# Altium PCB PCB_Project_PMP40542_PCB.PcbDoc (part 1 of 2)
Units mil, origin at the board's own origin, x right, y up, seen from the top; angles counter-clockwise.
Board outline 1181.1 x 1181.1 mil, 4 copper layers (Top Layer, Signal Layer 1, Signal Layer 2, Bottom Layer), stack 42.8 mil thick; 61 components, 38 nets, 268 pads, 149 vias.
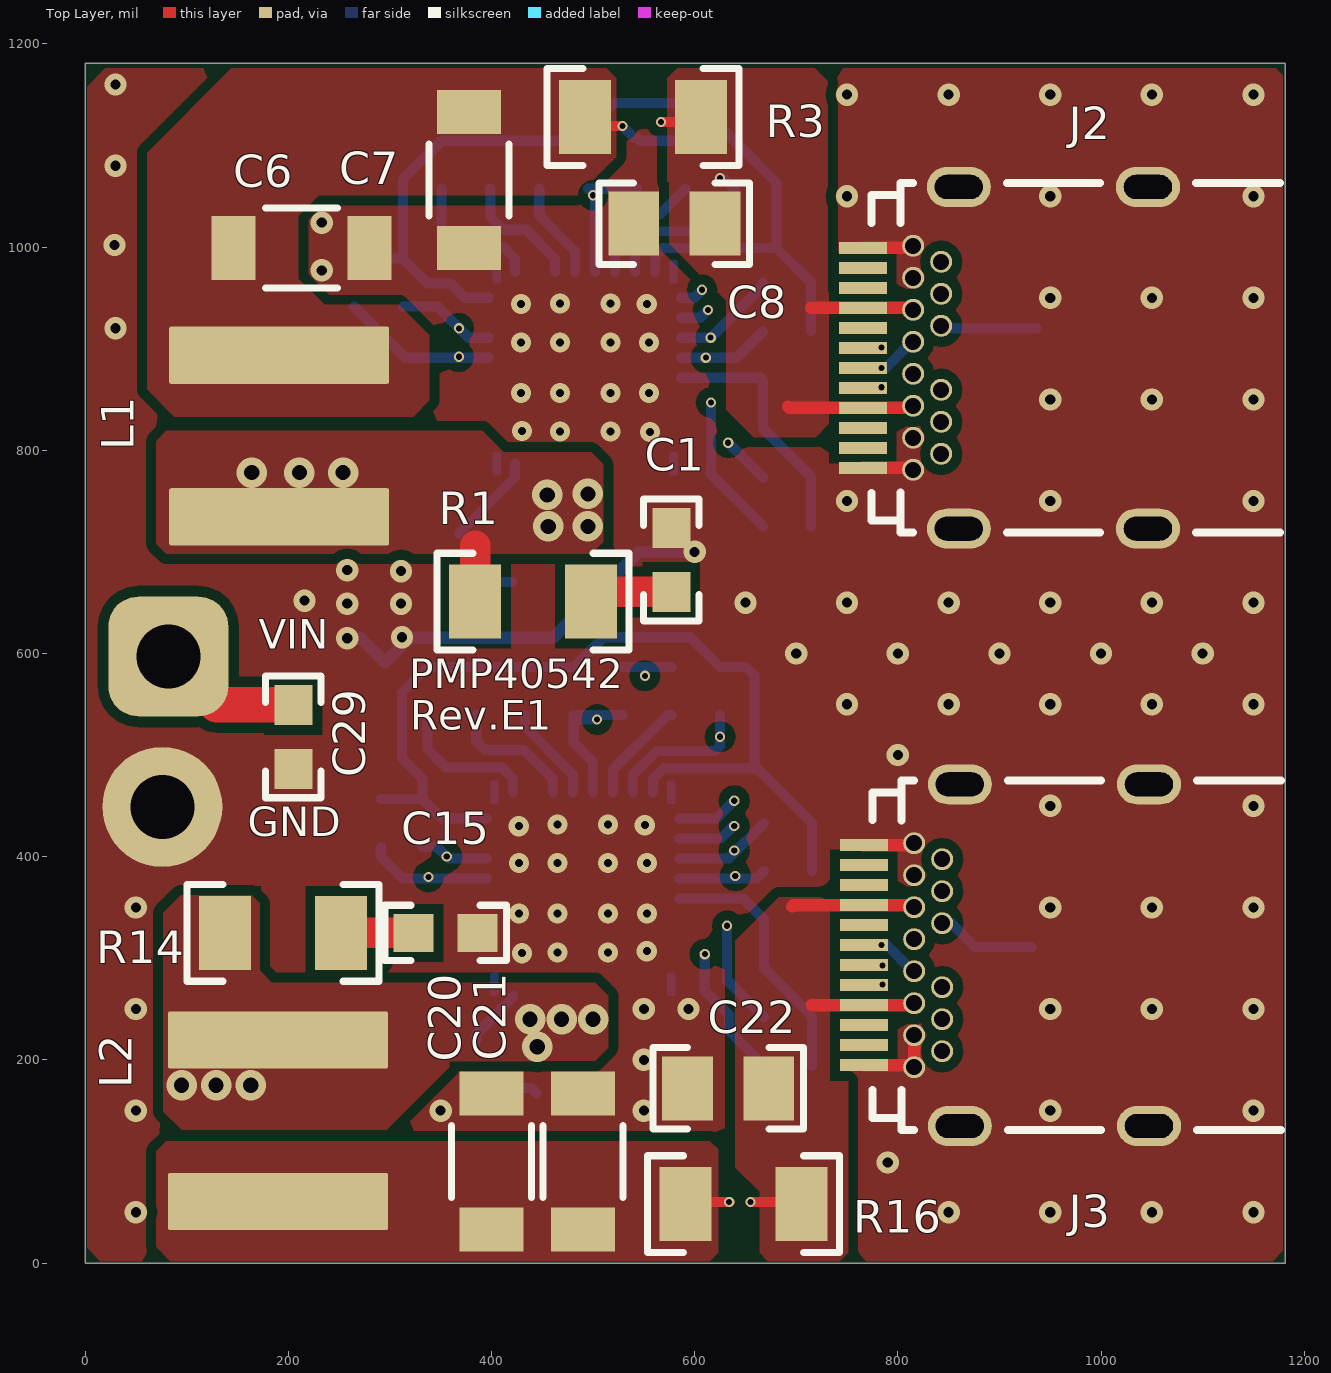
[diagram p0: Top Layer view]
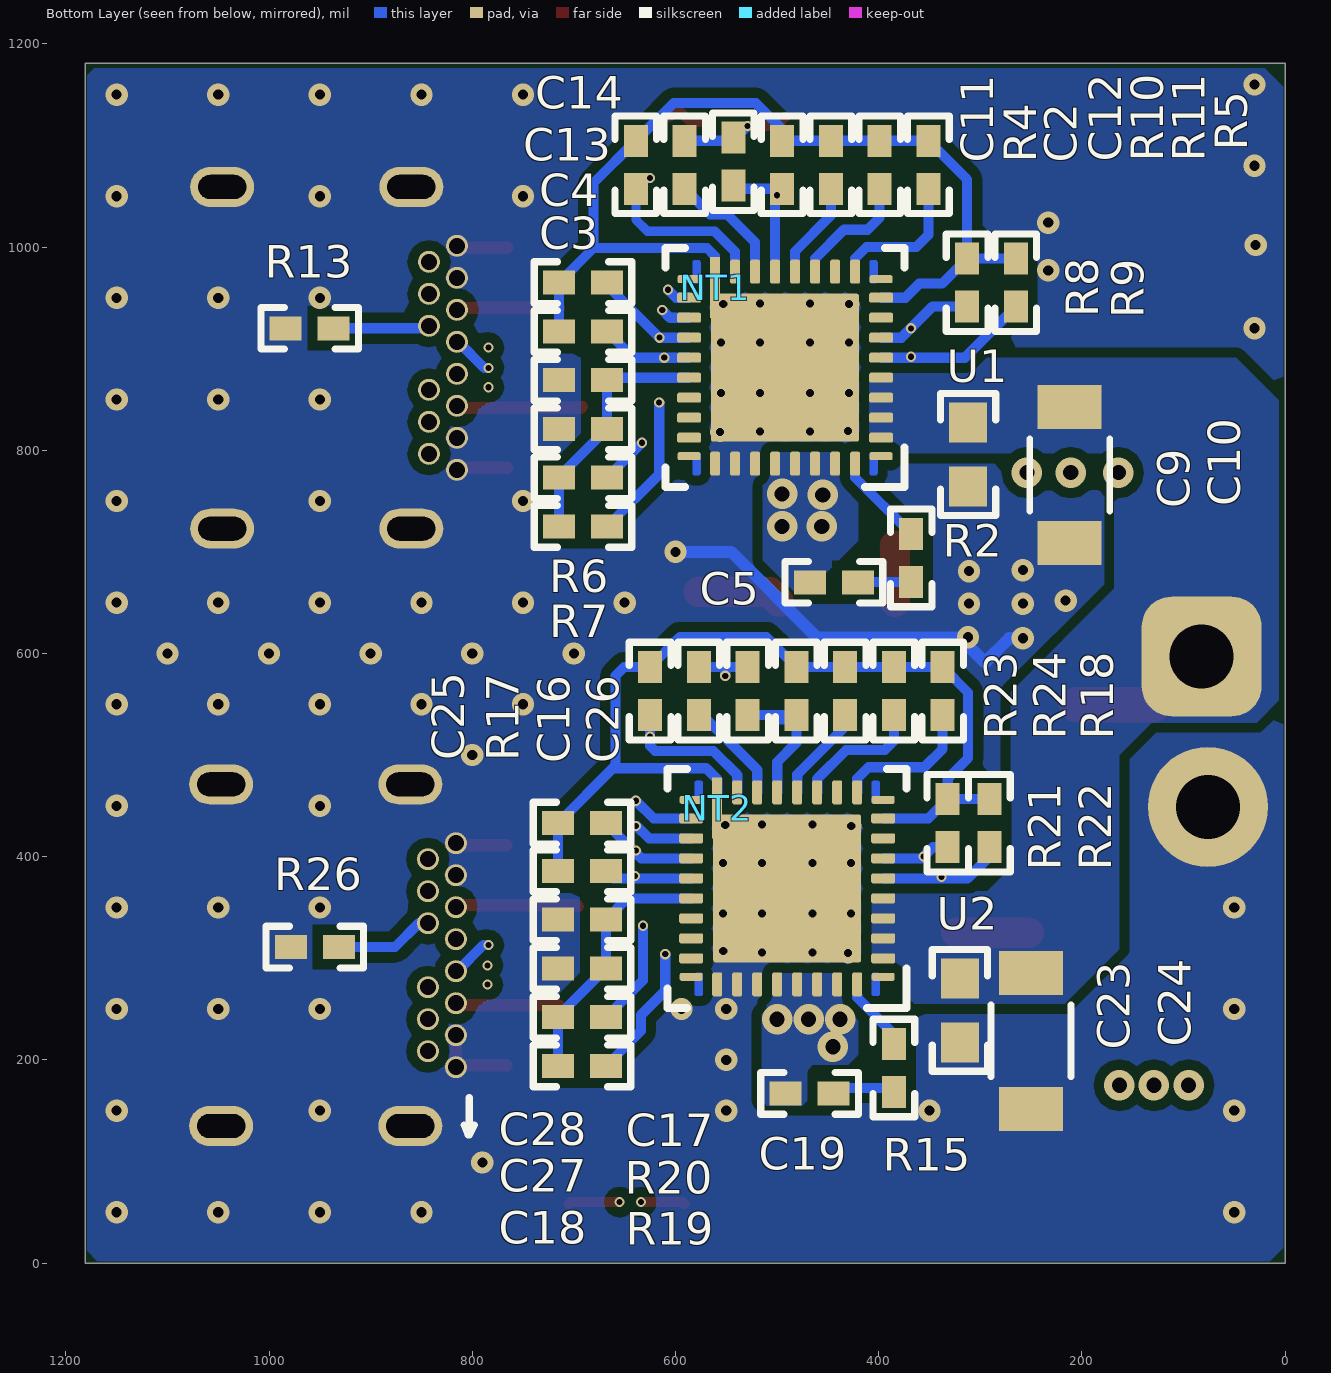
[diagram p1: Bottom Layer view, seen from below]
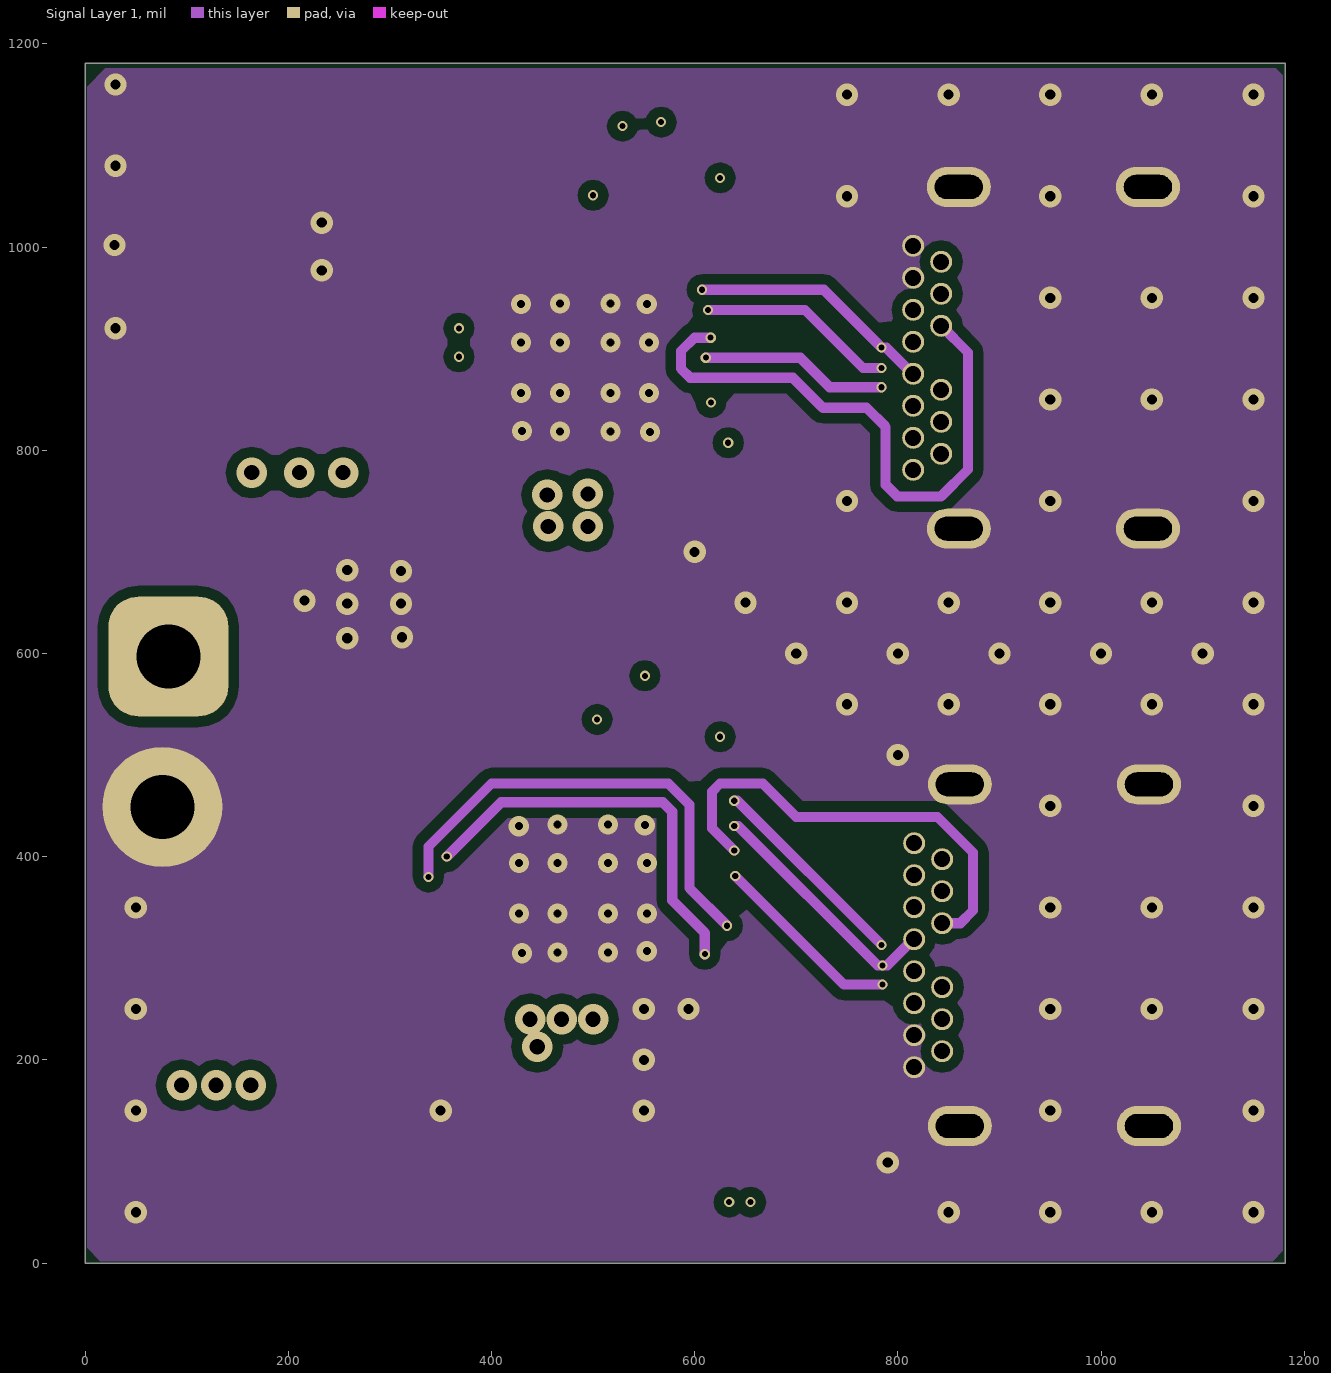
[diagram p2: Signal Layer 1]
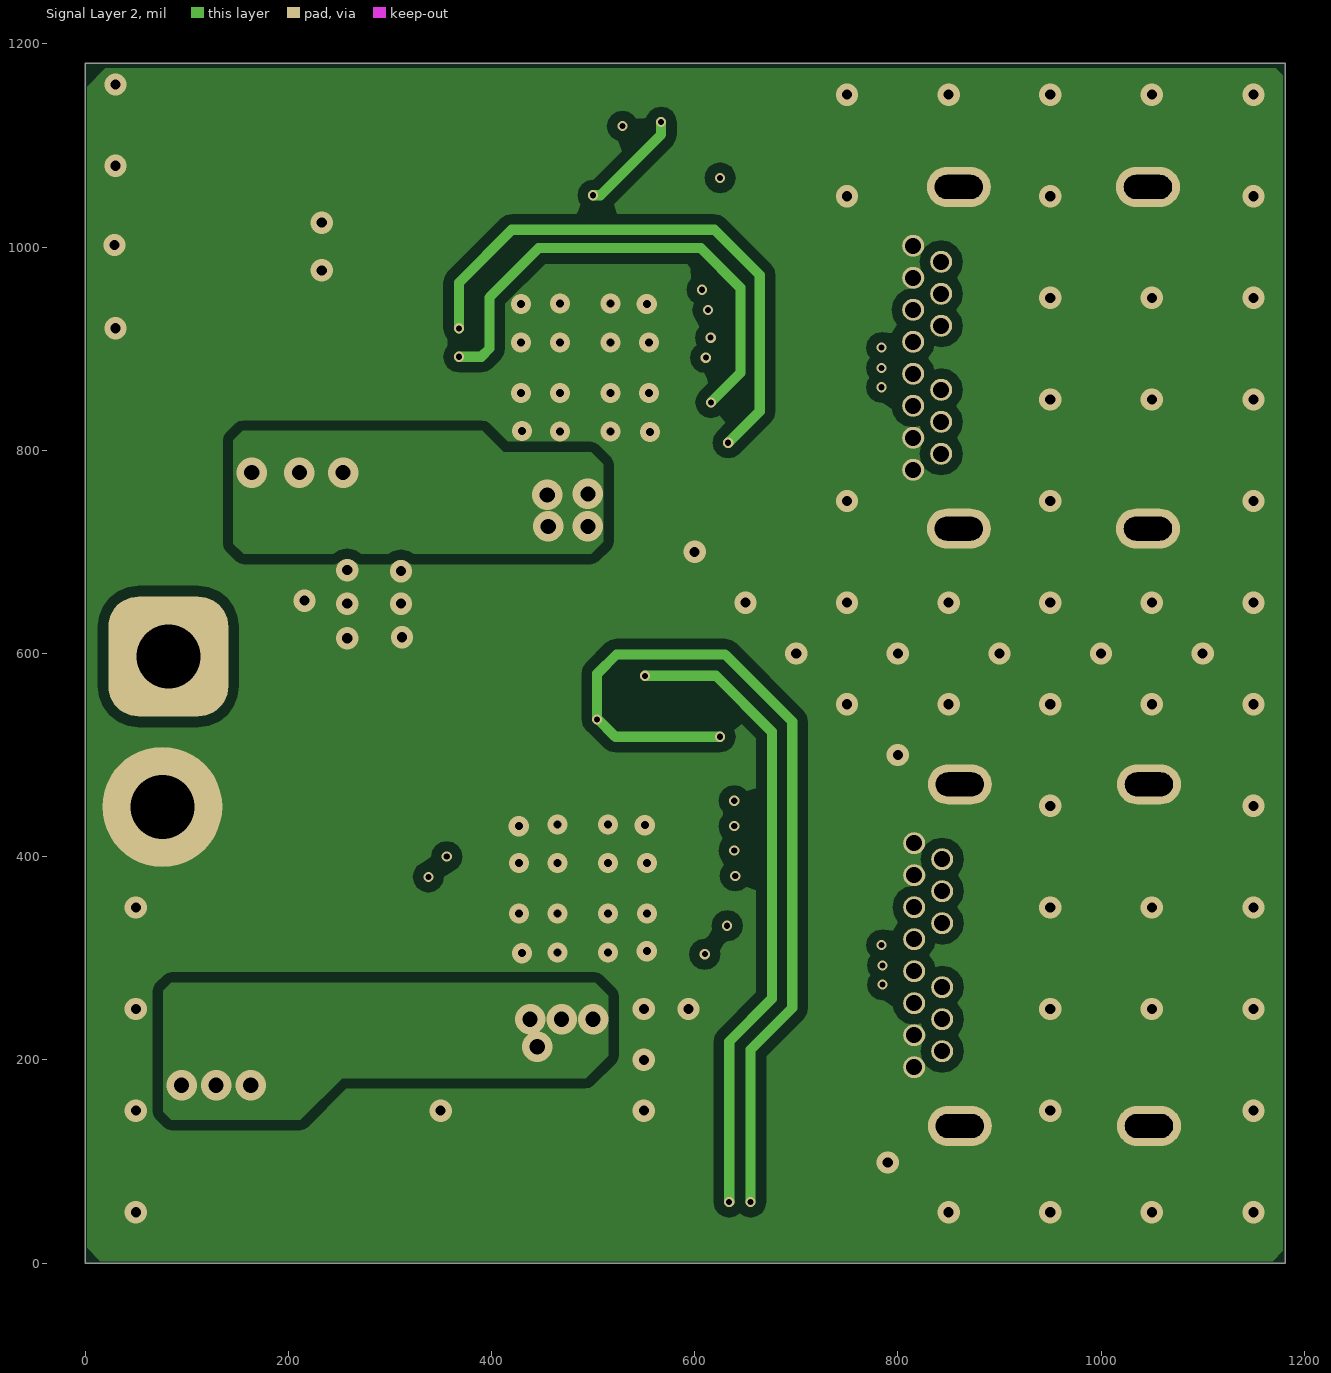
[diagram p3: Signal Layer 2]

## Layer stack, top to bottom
Top Solder: solder mask 0.4, Solder Resist, Dk 3.5
Top Layer: signal copper 2.8
Dielectric 1: prepreg 5, FR-4, Dk 4.2
Signal Layer 1: signal copper 1.4
Dielectric 2: core 24.4, FR-4, Dk 4.2
Signal Layer 2: signal copper 1.4
Dielectric 3: prepreg 5, FR-4, Dk 4.2
Bottom Layer: signal copper 2.8
Bottom Solder: solder mask 0.4, Solder Resist, Dk 3.5

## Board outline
0,0 1181.1,0 1181.1,1181.1 0,1181.1

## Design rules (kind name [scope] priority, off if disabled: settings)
AcuteAngle [All] p1: minimum=4.50000000000000E+0001 checktracksonly=FALSE
AssemblyTestPointUsage [All] p1: valid=2
Clearance Clearance_BoardEdge_MountingHoles [OnCopper and InComponentClass('Mounting Holes') vs IsKeepOut] p1: gap=40 ignorepadtopadclearanceinfootprint=FALSE except(0: Arc-Hole Track-Hole SMDPad-Hole THPad-Hole Via-Hole Fill-Hole Poly-Hole Region-Hole Text-Hole)
Clearance Clearance_BoardEdge_Poly [OnCopper and InPoly vs IsKeepOut] p2: gap=25 ignorepadtopadclearanceinfootprint=FALSE except(0: Arc-Hole Track-Hole SMDPad-Hole THPad-Hole Via-Hole Fill-Hole Poly-Hole Region-Hole Text-Hole)
Clearance Clearance_BoardEdge [OnCopper and Not InComponentClass('Logo') and not InComponentClass('FiducialMark') and not InRegion(1000,500,4000,800) and Not IsKeepout vs IsKeepOut] p3: gap=5 ignorepadtopadclearanceinfootprint=FALSE except(0: Arc-Hole Track-Hole SMDPad-Hole THPad-Hole Via-Hole Fill-Hole Poly-Hole Region-Hole Text-Hole)
Clearance Clearance_Poly [InPolygon] p4: gap=10 ignorepadtopadclearanceinfootprint=FALSE except(0: Arc-Hole Track-Hole SMDPad-Hole THPad-Hole Via-Hole Fill-Hole Poly-Hole Region-Hole Text-Hole)
Clearance [All] p5: gap=7 ignorepadtopadclearanceinfootprint=FALSE
ComponentClearance ComponentClearance_Logo [All] p1: gap=10 collisioncheckmode=3 verticalgap=10 showdistances=TRUE
ComponentClearance ComponentClearance_ScrewToNut [(HasFootprint('NY PMS 440 0025 PH')) vs (HasFootprint('Keystone_1902C'))] p2: gap=5 collisioncheckmode=3 verticalgap=10 showdistances=FALSE
ComponentClearance ComponentClearance_MountingHoles [InComponentClass('Mounting Holes')] p3: gap=10 collisioncheckmode=3 verticalgap=100000 showdistances=FALSE
ComponentClearance ComponentClearance_SmallPassives [HasFootprint('0201*') or HasFootprint('0402*') or HasFootprint('0508') or HasFootprint('0603*') or HasFootprint('0612') or HasFootprint('0805*') or HasFootprint('0815*') or HasFootprint('0830*') or HasFootprint('1206*') or HasFootprint('1210*') or HasFootprint('1808*') or HasFootprint('1812*') or HasFootprint('1825*') or HasFootprint('2010*') or HasFootprint('2220*') or HasFootprint('2225*') or HasFootprint('2512*') or HasFootprint('2728*') or HasFootprint('3518*') vs HasFootprint('0201*') or HasFootprint('0402*') or HasFootprint('0508') or HasFootprint('0603*') or HasFootprint('0612') or HasFootprint('0805*') or HasFootprint('0815*') or HasFootprint('0830*') or HasFootprint('1206*') or HasFootprint('1210*') or HasFootprint('1808*') or HasFootprint('1812*') or HasFootprint('1825*') or HasFootprint('2010*') or HasFootprint('2220*') or HasFootprint('2225*') or HasFootprint('2512*') or HasFootprint('2728*') or HasFootprint('3518*')] p4: gap=10 collisioncheckmode=3 verticalgap=10 showdistances=FALSE
ComponentClearance ComponentClearance_THtoSMT [IsThruComponent vs IsSMTComponent] p5: gap=10 collisioncheckmode=3 verticalgap=100000 showdistances=FALSE
ComponentClearance ComponentClearance_THtoTH [IsThruComponent vs IsThruComponent] p6: gap=10 collisioncheckmode=3 verticalgap=100000 showdistances=FALSE
ComponentClearance [All] p7: gap=10 collisioncheckmode=3 verticalgap=10 showdistances=FALSE
DiffPairsRouting [All] p1: maxlimit=100 minlimit=10 mostfreqgap=10 toplayer_minwidth=15 toplayer_maxwidth=15 toplayer_prefwidth=15 midlayer1_minwidth=15 midlayer1_maxwidth=15 midlayer1_prefwidth=15 midlayer2_minwidth=15 midlayer2_maxwidth=15 midlayer2_prefwidth=15 bottomlayer_minwidth=15 bottomlayer_maxwidth=15 bottomlayer_prefwidth=15 maxuncoupledlength=1000
FabricationTestPointUsage TestPointUsage [All] p1: valid=2 allowmultiple=FALSE
FabricationTestpoint Testpoint [All] p1: side=3 testpointundercomponent=TRUE minsize=40 maxsize=100 preferedsize=60 minholesize=0 maxholesize=40 preferedholesize=32 testpointgrid=1 allowsidetop=TRUE allowsidebottom=TRUE usegrid=TRUE gridtolerance=0.01
FanoutControl Fanout_LCC [IsLCC] p1: bgadir=Out bgaviamode=Centered fanoutstyle=Auto fanoutdirection=Alternating viagrid=1 // Fanout_LCC (Default Rule)
FanoutControl Fanout_BGA [IsBGA] p2: bgadir=Out bgaviamode=Centered fanoutstyle=Auto fanoutdirection=Alternating viagrid=1 // Fanout_BGA (Default Rule)
FanoutControl Fanout_Default [All] p4: bgadir=Out bgaviamode=Centered fanoutstyle=Auto fanoutdirection=Alternating viagrid=1 // Fanout_Default (Default Rule)
FanoutControl Fanout_Small [(CompPinCount < 5)] p5: bgadir=Out bgaviamode=Centered fanoutstyle=Auto fanoutdirection=OutThenIn viagrid=1 // Fanout_Small (Default Rule)
HoleSize [All] p1: absolutevalues=TRUE maxlimit=251 minlimit=6 maxpercent=80.000 minpercent=20.000
MinimumAnnularRing [All] p1: minimumring=2
MinimumSolderMaskSliver MinimumSolderMaskSliver_Logo [InComponentClass('Logo') vs InComponentClass('Logo')] p1: minsoldermaskwidth=0.7
MinimumSolderMaskSliver [All] p2: minsoldermaskwidth=0
PlaneConnect [All] p1: planeconnectstyle=Direct reliefexpansion=10 reliefentries=4 reliefconductorwidth=10 reliefairgap=10
PolygonConnect [All] p1: connectstyle=Direct reliefconductorwidth=10 reliefentries=4 polygonreliefangle="90 Angle" airgapwidth=10
RoutingCorners [All] p1: cornerstyle=45-Degree minsetback=10 maxsetback=100
RoutingVias [All] p1: holewidth=16 width=34 viastyle="Through Hole" minholewidth=6 minwidth=10 maxholewidth=40 maxwidth=65
SMDToCorner [All] p1: distance=0
SilkToBoardRegionClearance [Not ((IsComment or IsDesignator) And (Hide <> 'False')) and not InRegion(1000,500,4000,800)] p1:
SilkToSilkClearance [All] p1: silktosilkclearance=0
SilkToSolderMaskClearance SilkscreenOverComponentPads [IsPad] p1: minsilkscreentomaskgap=0 clearancetoexposedcopper=TRUE
SolderMaskExpansion [All] p1: expansion=3
Width [All] p1: maxlimit=100 minlimit=6 preferedwidth=10 checkconnectedcopper=TRUE
14 further rules are at their usual default settings.

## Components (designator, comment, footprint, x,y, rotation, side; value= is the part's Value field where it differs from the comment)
C1 "GCM1885C2A101JA16D" 0603 577,692 r270 top value=100pF
C2 "CGA2B3X7R1E104K050BB" 0402 543,1084 r270 bottom value=0.1uF
C3 "GRT155R61E225KE13D" 0402 691,821 r0 bottom value=2.2uF
C4 "CGA2B3X7R1E104K050BB" 0402 691,869 r0 bottom value=0.1uF
C5 "CGA2B3X7R1E104K050BB" 0402 444,670 r0 bottom value=0.1uF
C6 "GRT31CR61E226KE01L" 1206_180 213,999 r0 top value=22uF
C7 "GRT31CR61E226KE01L" 1206_180 378,1066 r270 top value=22uF
C8 "GRM21BC81C106KA73L" 0805_HV 580,1023 r180 top value=10uF
C9 "CGA3E2X7R1H104K080AA" 0603 312,795.74 r270 bottom value=0.1uF
C10 "CGA5L1X7R1H106K160AC" 1206_190 212,775.74 r270 bottom value=10uF
C11 "C1005X5R1E224M050BC" 0402 639,1081 r90 bottom value=0.22uF
C12 "CGA2B3X7R1E104K050BB" 0402 495,1081 r270 bottom value=0.1uF
C13 "C1005X5R1E224M050BC" 0402 691,917 r0 bottom value=0.22uF
C14 "C1005X5R1E224M050BC" 0402 691,965 r0 bottom value=0.22uF
C15 "GCM1885C2A101JA16D" 0603 355,325 r180 top value=100pF
C16 "CGA2B3X7R1E104K050BB" 0402 529,563 r270 bottom value=0.1uF
C17 "GRT155R61E225KE13D" 0402 692,290 r0 bottom value=2.2uF
C18 "CGA2B3X7R1E104K050BB" 0402 692,338 r0 bottom value=0.1uF
C19 "CGA2B3X7R1E104K050BB" 0402 468,167 r0 bottom value=0.1uF
C20 "GRT31CR61E226KE01L" 1206_180 400,100 r90 top value=22uF
C21 "GRT31CR61E226KE01L" 1206_180 490,100 r90 top value=22uF
C22 "GRM21BC81C106KA73L" 0805_HV 633,172 r180 top value=10uF
C23 "CGA3E2X7R1H104K080AA" 0603 320,248.74 r270 bottom value=0.1uF
C24 "CGA5L1X7R1H106K160AC" 1206_190 250,218.74 r270 bottom value=10uF
C25 "C1005X5R1E224M050BC" 0402 625,563 r90 bottom value=0.22uF
C26 "CGA2B3X7R1E104K050BB" 0402 481,563 r270 bottom value=0.1uF
C27 "C1005X5R1E224M050BC" 0402 692,386 r0 bottom value=0.22uF
C28 "C1005X5R1E224M050BC" 0402 692,433 r0 bottom value=0.22uF
C29 "CGA3E2X7R1H104K080AA" 0603 205,518 r270 top value=0.1uF
J2 "632723300011" Wurth_632_723_300_011 1182,891 r90 top locked
J3 "632723300011" Wurth_632_723_300_011 1183,303 r90 top locked
L1 "XAL6060-103MEB" XAL6060 191,814 r90 top value=10uH
L2 "XAL6060-103MEB" XAL6060 190,140 r270 top value=10uH
NT1 "Net-Tie" Net-Tie_10milWide_30milLong 561,960 r90 bottom net-tie
NT2 "Net-Tie" Net-Tie_10milWide_30milLong 559,448 r90 bottom net-tie
R1 "ERJ-8ENF10R0V" 1206 441,651 r0 top value=10.0
R2 "ERJ-2GE0R00X" 0402 368,694 r270 bottom value=0
R3 "CSR1206FK15L0" 1206 549,1128 r0 top value=0.015
R4 "CRCW0402301RFKED" 0402 591,1081 r90 bottom value=301
R5 "ERJ-2RKF4992X" 0402 351,1081 r270 bottom value=49.9k
R6 "CRCW0402100KFKED" 0402 691,773 r0 bottom value=100k
R7 "CRCW0402100KFKED" 0402 691,725 r0 bottom value=100k
R8 "ERJ-2GE0R00X" 0402 313,965 r270 bottom value=0
R9 "ERJ-2GE0R00X" 0402 265,965 r270 bottom value=0
R10 "CRCW040212K1FKED" 0402 447,1081 r270 bottom value=12.1k
R11 "CRCW040213K0FKED" 0402 399,1081 r270 bottom value=13.0k
R13 "CRCW04025K10JNED" 0402 960,920 r180 bottom value=5.1k
R14 "ERJ-8ENF10R0V" 1206 195,325 r0 top value=10.0
R15 "ERJ-2GE0R00X" 0402 385,192 r270 bottom value=0
R16 "CSR1206FK15L0" 1206 648,58 r0 top value=0.015
R17 "CRCW0402301RFKED" 0402 577,563 r90 bottom value=301
R18 "ERJ-2RKF4992X" 0402 337,563 r270 bottom value=49.9k
R19 "CRCW0402100KFKED" 0402 692,194 r0 bottom value=100k
R20 "CRCW0402100KFKED" 0402 692,242 r0 bottom value=100k
R21 "ERJ-2GE0R00X" 0402 332,433 r270 bottom value=0
R22 "ERJ-2GE0R00X" 0402 291,433 r270 bottom value=0
R23 "CRCW040212K1FKED" 0402 433,563 r270 bottom value=12.1k
R24 "CRCW040213K0FKED" 0402 385,563 r270 bottom value=13.0k
R26 "CRCW04025K10JNED" 0402 955,311 r180 bottom value=5.1k
U1 "PTPS25833QWRHBTQ1" RHB0032R 492.16,881.25 r0 bottom
U2 "PTPS25833QWRHBTQ1" RHB0032R 490,368.74 r0 bottom

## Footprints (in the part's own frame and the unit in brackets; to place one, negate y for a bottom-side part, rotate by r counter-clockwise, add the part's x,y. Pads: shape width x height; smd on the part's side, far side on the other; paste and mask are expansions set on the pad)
0402 [mm] "0402 from SM-752 data"
  rect 0.8x0.6 smd: 1(-0.6,0) 2(0.6,0)
  silkscreen extent -1.22,-0.52 1.22,0.52, body extent -0.55,-0.3 0.55,0.3, height 0.6
0603 [mm] "0603 from SM-752 data"
  rect 1x0.95 smd: 1(-0.8,0) 2(0.8,0)
  silkscreen extent -1.52,-0.69 1.52,0.69, body extent -0.87,-0.47 0.87,0.47, height 1
0805_HV [mil] "0805 with 30mil clearance between pads"
  rect 50x63 smd: 1(-40,0) 2(40,0)
  silkscreen extent -74,-40 74,40, body extent -43,-29 43,29, height 57
1206 [mm] "1206 from SM-752 data"
  rect 1.3x1.85 smd: 1(-1.45,0) 2(1.45,0)
  silkscreen extent -2.4,-1.21 2.4,1.21, body extent -1.7,-0.9 1.7,0.9, height 1.35
1206_180 [mm] "1206_180"
  rect 1.1x1.6 smd: 1(-1.7,0) 2(1.7,0)
  silkscreen extent -0.9,-1 0.9,1, body extent -1.75,-0.95 1.75,0.95, height 1.8
1206_190 [mm] "1206_190"
  rect 1.1x1.6 smd: 1(-1.7,0) 2(1.7,0)
  silkscreen extent -0.9,-1 0.9,1, body extent -1.75,-0.95 1.75,0.95, height 1.9
Net-Tie_10milWide_30milLong [mil] "10mil net tie, no solder mask opening, no solder paste"
  rect 30x10 smd paste-5 mask-5: 1(-15,0) 2(15,0)
RHB0032R [mm] "QFN, 32-Leads, Body 5x5mm, Pitch 0.5mm, Thermal Pad 3.7x3.7mm"
  rrect40% 0.6x0.25 smd: 1(-2.4,1.75) 2(-2.4,1.25) 3(-2.4,0.75) 4(-2.4,0.25) 5(-2.4,-0.25) 6(-2.4,-0.75) 7(-2.4,-1.25) 8(-2.4,-1.75) 17(2.4,-1.75) 18(2.4,-1.25) 19(2.4,-0.75) 20(2.4,-0.25) 21(2.4,0.25) 22(2.4,0.75) 23(2.4,1.25) 24(2.4,1.75)
  rrect40% 0.25x0.6 smd: 9(-1.75,-2.4) 10(-1.25,-2.4) 11(-0.75,-2.4) 12(-0.25,-2.4) 13(0.25,-2.4) 14(0.75,-2.4) 15(1.25,-2.4) 16(1.75,-2.4) 25(1.75,2.4) 26(1.25,2.4) 27(0.75,2.4) 28(0.25,2.4) 29(-0.25,2.4) 30(-0.75,2.4) 31(-1.25,2.4) 32(-1.75,2.4)
  rrect9% 1.06x1.06 on Bottom Paste: 33(-1.26,-1.26) 33(-1.26,0) 33(-1.26,1.26) 33(0,-1.26) 33(0,0) 33(0,1.26) 33(1.26,-1.26) 33(1.26,0) 33(1.26,1.26)
  rrect3% 3.7x3.7 smd paste-2: 33(0,0)
  rrect50% 0.575x0.2 smd: A1(-2.4,2.213) A2(-2.4,-2.213) A3(2.4,-2.213) A4(2.4,2.213)
  Top Layer region: 2.113,-2.638 2.113,-2.163 2.116,-2.143 2.127,-2.127 2.143,-2.116 2.163,-2.113 2.163,-2.113 2.262,-2.113 2.282,-2.116 2.298,-2.127 2.309,-2.143 2.312,-2.163 2.312,-2.163 2.312,-2.638 2.309,-2.657 2.298,-2.673 2.282,-2.684 2.262,-2.688 2.262,-2.688 2.163,-2.688 2.143,-2.684 2.127,-2.673 2.116,-2.657 2.113,-2.638
  Top Layer region: -2.113,-2.638 -2.113,-2.163 -2.116,-2.143 -2.127,-2.127 -2.143,-2.116 -2.163,-2.113 -2.163,-2.113 -2.262,-2.113 -2.282,-2.116 -2.298,-2.127 -2.309,-2.143 -2.312,-2.163 -2.312,-2.163 -2.312,-2.638 -2.309,-2.657 -2.298,-2.673 -2.282,-2.684 -2.262,-2.688 -2.262,-2.688 -2.163,-2.688 -2.143,-2.684 -2.127,-2.673 -2.116,-2.657 -2.113,-2.638
  Top Layer region: -2.113,2.638 -2.113,2.163 -2.116,2.143 -2.127,2.127 -2.143,2.116 -2.163,2.113 -2.163,2.113 -2.262,2.113 -2.282,2.116 -2.298,2.127 -2.309,2.143 -2.312,2.163 -2.312,2.163 -2.312,2.638 -2.309,2.657 -2.298,2.673 -2.282,2.684 -2.262,2.688 -2.262,2.688 -2.163,2.688 -2.143,2.684 -2.127,2.673 -2.116,2.657 -2.113,2.638
  Top Layer region: 2.113,2.638 2.113,2.163 2.116,2.143 2.127,2.127 2.143,2.116 2.163,2.113 2.163,2.113 2.262,2.113 2.282,2.116 2.298,2.127 2.309,2.143 2.312,2.163 2.312,2.163 2.312,2.638 2.309,2.657 2.298,2.673 2.282,2.684 2.262,2.688 2.262,2.688 2.163,2.688 2.143,2.684 2.127,2.673 2.116,2.657 2.113,2.638
  silkscreen extent -2.99,-2.99 2.99,2.99, body extent -2.5,-2.5 2.5,2.5, height 1
Wurth_632_723_300_011 [mm] "Connector, Receptacle, USB Type C, R/A"
  rect 0.3x1.2 smd: A1(-2.75,10.58) A2(-2.25,10.58) A3(-1.75,10.58) A4(-1.25,10.58) A5(-0.75,10.58) A6(-0.25,10.58) A7(0.25,10.58) A8(0.75,10.58) A9(1.25,10.58) A10(1.75,10.58) A11(2.25,10.58) A12(2.75,10.58)
  round 0.55 hole 0.4: B1(2.8,9.32) B2(2.4,8.62) B3(1.6,8.62) B4(1.2,9.32) B5(0.8,8.62) B6(0.4,9.32) B7(-0.4,9.32) B8(-0.8,8.62) B9(-1.2,9.32) B10(-1.6,8.62) B11(-2.4,8.62) B12(-2.8,9.32) M1(2,9.32) M2(-2,9.32)
  rrect100% 1x1.6 hole 0.6 slot 1.2 at 90 deg: S1(-4.27,8.18) S2(-4.27,3.45) S3(4.27,3.45) S4(4.27,8.18)
  silkscreen extent -4.37,0.15 4.37,10.36, body extent -4.37,-0.96 4.37,10.83, height 3.07
XAL6060 [mm] "Coilcraft recommended land pattern Document 887-4 Revised 01/14/18"
  rrect7% 1.43x5.5 smd: 1(-2.019,0) 2(2.019,0)
  body extent -3.28,-3.38 3.28,3.38, height 6.11

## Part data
C1 C15: library part CMP-0007130-4, "CAP, CERM, 100 pF, 100 V, +/- 5%, C0G/NP0, AEC-Q200 Grade 1, 0603", Cap_Case=0603, Manufacturer=MuRata, Supplier Part Number 1=490-4771-1-ND, TempCo=C0G/NP0, Tolerance_%=5%, Value1=Unknown, Value2=100V, ValueDisplayed=100pF
C2 C4 C5 C12 C16 C18 C19 C26: library part CMP-0080610-1, "CAP, CERM, 0.1 µF, 25 V,+/- 10%, X7R, AEC-Q200 Grade 1, 0402", Cap_Case=0402, Manufacturer=TDK, Supplier Part Number 1=445-6902-1-ND, TempCo=X7R, Tolerance_%=10%, Value2=25V, ValueDisplayed=0.1µF
C3 C17: library part CMP-0006716-2, "CAP, CERM, 2.2 uF, 25 V, +/- 10%, X5R, AEC-Q200 Grade 3, 0402", Cap_Case=0402, Manufacturer=MuRata, Supplier Part Number 1=490-12267-1-ND, TempCo=X5R, Tolerance_%=10%, Value1=Unknown, Value2=25V, ValueDisplayed=2.2uF
C6 C7 C20 C21: library part CMP-0009014-2, "CAP, CERM, 22 uF, 25 V, +/- 10%, X5R, AEC-Q200 Grade 3, 1206", Cap_Case=1206, Manufacturer=MuRata, Supplier Part Number 1=490-12450-1-ND, TempCo=X5R, Tolerance_%=10%, Value1=Unknown, Value2=25V, ValueDisplayed=22uF
C8 C22: library part CMP-0081634-1, "CAP, CERM, 10 µF, 16 V,+/- 10%, X6S, 0805", Cap_Case=0805, Manufacturer=MuRata, Supplier Part Number 1=490-5519-1-ND, TempCo=X6S, Tolerance_%=10%, Value1="0.001 ohm", Value2=16V, ValueDisplayed=10µF
C9 C23 C29: library part CMP-0007078-4, "CAP, CERM, 0.1 uF, 50 V, +/- 10%, X7R, AEC-Q200 Grade 1, 0603", Cap_Case=0603, Manufacturer=TDK, Supplier Part Number 1=445-5666-1-ND, TempCo=X7R, Tolerance_%=10%, Value1="0.0296 ohm", Value2=50V, ValueDisplayed=0.1uF
C10 C24: library part CMP-0085950-1, "CAP, CERM, 10 µF, 50 V,+/- 10%, X7R, AEC-Q200 Grade 1, 1206", Cap_Case=1206, Manufacturer=TDK, TempCo=X7R, Tolerance_%=10%, Value2=50V, ValueDisplayed=10µF
C11 C13 C14 C25 C27 C28: library part CMP-0006277-2, "CAP, CERM, 0.22 uF, 25 V, +/- 20%, X5R, 0402", Cap_Case=0402, Manufacturer=TDK, Supplier Part Number 1=445-5945-1-ND, TempCo=X5R, Tolerance_%=20%, Value1=Unknown, Value2=25V, ValueDisplayed=0.22uF
J2 J3: library part CMP-0080891-1, "Connector, Receptacle, USB Type C, R/A", Color=Black, Current_A=3A, Manufacturer="Wurth Elektronik", Supplier Part Number 1=732-9618-1-ND, Voltage_V=5V
L1 L2: library part CMP-0061019-2, "Inductor, Shielded, Composite, 10 µH, 7 A, 0.02982 ohm, AEC-Q200 Grade 1, SMD", Manufacturer=Coilcraft, Value1="0.02982 ohm", Value2=7.6A, ValueDisplayed=10uH
NT1 NT2: library part CMP-0078142-2, "Single point connection between nets.", Manufacturer=N/A
R1 R14: library part CMP-0017299-3, "RES, 10.0, 1%, 0.25 W, AEC-Q200 Grade 0, 1206", Manufacturer=Panasonic, Power_W=250mW, Supplier Part Number 1=P10.0FCT-ND, TempCo="100 ppm/C", Tolerance_%=1%, Value2=0.25W, Value_Code=10R0, ValueDisplayed=10.0
R2 R8 R9 R15 R21 R22: library part CMP-0026992-3, "RES, 0, 5%, 0.1 W, AEC-Q200 Grade 0, 0402", Manufacturer=Panasonic, Power_W=100mW, Supplier Part Number 1=P0.0JCT-ND, TempCo="600 ppm/C", Tolerance_%=5%, Value2=0.1W, Value_Code=0000, ValueDisplayed=0
R3 R16: library part CMP-0017258-2, "RES, 0.015, 1%, 0.5 W, 1206", Manufacturer="Stackpole Electronics Inc", Power_W=500mW, Supplier Part Number 1=CSR1206FK15L0CT-ND, TempCo="100 ppm/C", Tolerance_%=1%, Value2=0.5W, Value_Code=R015, ValueDisplayed=0.015
R4 R17: library part CMP-0026281-2, "RES, 301, 1%, 0.063 W, AEC-Q200 Grade 0, 0402", Manufacturer=Vishay-Dale, Power_W=63mW, Supplier Part Number 1=541-301LCT-ND, TempCo="100 ppm/C", Tolerance_%=1%, Value2=0.063W, Value_Code=301R, ValueDisplayed=301
R5 R18: library part CMP-0026702-1, "RES, 49.9 k, 1%, 0.1 W, AEC-Q200 Grade 0, 0402", Manufacturer=Panasonic, Power_W=100mW, Supplier Part Number 1=P49.9KLCT-ND, TempCo="100 ppm/C", Tolerance_%=1%, Value2=0.1W, Value_Code=49k9, ValueDisplayed=49.9k
R6 R7 R19 R20: library part CMP-0025950-3, "RES, 100 k, 1%, 0.063 W, AEC-Q200 Grade 0, 0402", Manufacturer=Vishay-Dale, Power_W=63mW, Supplier Part Number 1=541-100KLCT-ND, TempCo="100 ppm/C", Tolerance_%=1%, Value2=0.063W, Value_Code=100k
R10 R23: library part CMP-0025991-3, "RES, 12.1 k, 1%, 0.063 W, AEC-Q200 Grade 0, 0402", Manufacturer=Vishay-Dale, Power_W=63mW, Supplier Part Number 1=541-12.1KLCT-ND, TempCo="100 ppm/C", Tolerance_%=1%, Value2=0.063W, Value_Code=12k1, ValueDisplayed=12.1k
R11 R24: library part CMP-0026003-3, "RES, 13.0 k, 1%, 0.063 W, AEC-Q200 Grade 0, 0402", Manufacturer=Vishay-Dale, Power_W=63mW, Supplier Part Number 1=541-13.0KLCT-ND, TempCo="100 ppm/C", Tolerance_%=1%, Value2=0.063W, Value_Code=13k0, ValueDisplayed=13.0k
R13 R26: library part CMP-0026951-5, "RES, 5.1 k, 5%, 0.063 W, AEC-Q200 Grade 0, 0402", Manufacturer=Vishay-Dale, Power_W=63mW, Supplier Part Number 1=541-5.1KJCT-ND, TempCo="200 ppm/C", Tolerance_%=5%, Value2=0.063W, Value_Code=5k10, ValueDisplayed=5.1k
U1 U2: library part CMP-0079842-1, "USB Type-C and BC1.2 5V 3.5A Output, 36V Input Synchronous Buck with Cable Compensation, RHB0032R (VQFN-32)", Alternate Manufacturer="Texas Instruments"

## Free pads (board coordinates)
  rrect50% 118.11x118.11 hole 62.99: 1(82,597)
  round 118.11 hole 62.99: 2(76,449)

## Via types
v1: diameter 22, hole 10, Top Layer to Bottom Layer, tented both sides, 72 vias
v2: diameter 10, hole 6, Top Layer to Bottom Layer, tented both sides, 31 vias
v3: diameter 19.68, hole 7.87, Top Layer to Bottom Layer, 24 vias
v4: diameter 30, hole 15, Top Layer to Bottom Layer, 14 vias
v5: diameter 20, hole 8, Top Layer to Bottom Layer, tented both sides, 8 vias

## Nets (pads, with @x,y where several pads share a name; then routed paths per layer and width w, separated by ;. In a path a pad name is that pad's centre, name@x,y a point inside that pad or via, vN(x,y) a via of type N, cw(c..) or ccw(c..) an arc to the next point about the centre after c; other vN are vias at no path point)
AGND1: C11.2 C12.1 C13.2 C14.2 NT1.2 R5.1 R8.1 R9.1 R10.1 R11.1 U1.8 U1.16 | length 963
  Bottom Layer w10: R9.1@265,988.62 R8.1@313,988.62 ; U1.8@397.67,950.15 373.85,950.15 360,964 337.62,964 R8.1@313,988.62 ; U1.16@561.06,975.74 561.06,991.06 569,999 571.45,999 571.51,999.06 587.02,999.06 587.08,999 680.62,999 ; C13.2@714.62,917 C14.2@714.62,965 680.62,999 ; R8.1@313,988.62 313,1066.62 R5.1@351,1104.62 R11.1@399,1104.62 R10.1@447,1104.62 C12.1@495,1104.62 495,1116 520.81,1141.81 601.82,1141.81 C11.2@639,1104.62 680.62,1063 680.62,999
AGND2: C25.2 C26.1 C27.2 C28.2 NT2.2 R18.1 R21.1 R22.1 R23.1 R24.1 U2.8 U2.16 | length 946.5
  Bottom Layer w10: R22.1@291,456.62 R21.1@332,456.62 ; U2.8@395.51,437.64 350.98,437.64 R21.1@332,456.62 ; U2.16@558.9,463.23 558.9,476.09 569.8,487 661.62,487 ; C27.2@715.62,386 C28.2@715.62,433 661.62,487 ; R21.1@332,456.62 332,477 312,497 312,561.62 R18.1@337,586.62 R24.1@385,586.62 R23.1@433,586.62 C26.1@481,586.62 510.38,616 595.62,616 C25.2@625,586.62 650.38,586.62 659,578 659,489.62 661.62,487
CC1_1: C13.1 J2.A5 U1.20 | length 276.5
  Signal Layer 1 w10: v2(611,891.09) 703.91,891.09 733,862 v2(784,862)
  Bottom Layer w10: U1.20@586.65,891.09 v2(611,891.09) 641.47,891.09 C13.1@667.38,917
CC1_2: C27.1 J3.A5 U2.20 | length 276.3
  Signal Layer 1 w10: v2(640,381) 747,274 v2(785,274)
  Bottom Layer w10: U2.20@584.49,378.58 660.96,378.58 C27.1@668.38,386
CC2_1: C14.1 J2.B5 R13.2 U1.19 | length 782.6
  Signal Layer 1 w10: v2(615.78,910.78) 599.78,910.78 586.65,897.65 586.65,880.35 595.59,871.41 696.59,871.41 726.21,841.79 769.21,841.79 788,823 788,766 799.43,754.57 842.57,754.57 869,781 869,896.13 J2.B5@842.63,922.5
  Bottom Layer w10: U1.19@586.65,910.78 v2(615.78,910.78) 667.38,962.38 C14.1@667.38,965 ; J2.B5@842.63,922.5 845.13,920 R13.2@936.38,920
CC2_2: C28.1 J3.B5 R26.2 U2.19 | length 643.9
  Signal Layer 1 w10: 622,422.96 v2(639,406) ; 622,423 617,428 617,464 625,472 667.04,472 700.04,439 839,439 874,404 874,347 861.5,334.5 J3.B5@843.63,334.5
  Bottom Layer w10: U2.19@584.49,398.27 633.65,398.27 C28.1@668.38,433 ; J3.B5@843.63,334.5 852.5,334.5 876,311 R26.2@931.38,311
CSN_1: C2.2 C8.1 C11.1 C12.2 J2.A4 J2.A9 J2.B4 J2.B9 R3.2 U1.13 U1.15 | length 680.6
  Top Layer w10: v2(567,1123) 585.09,1123 598.09,1136 R3.2@606.09,1128
  Top Layer w12: 692,843 693.21,841.79 J2.A4@765.46,841.79 813.1,841.79 J2.B9@815.07,843.76 ; 714.62,940 714.83,940.21 J2.A9@765.46,940.21 813.1,940.21 J2.B4@815.07,938.24
  Signal Layer 2 w10: v2(500,1051) 507.26,1051 567,1110.74 v2(567,1123)
  Bottom Layer w9: 561.37,1014.71 562.17,1015.5 564.62,1015.5 564.67,1015.56 593.85,1015.56 593.91,1015.5 627.5,1015.5 639,1027 C11.1@639,1057.38
  Bottom Layer w10: C12.2@495,1057.38 C2.2@543,1057.38 ; v2(500,1051) 502,1049 U1.13@502,975.74 ; U1.15@541.37,975.74 541.37,995.41 561.02,1015.06 ; v2(625,1068) 628.38,1068 C11.1@639,1057.38
CSN_2: C16.2 C22.1 C25.1 C26.2 J3.A4 J3.A9 J3.B4 J3.B9 R16.2 U2.13 U2.15 | length 1465.9
  Top Layer w10: v2(655,60) 703.09,60 R16.2@705.09,58
  Top Layer w12: 696,351 697.21,352.21 J3.A9@766.46,352.21 814.1,352.21 J3.B4@816.07,350.24 ; 715,254 715.21,253.79 J3.A4@766.46,253.79 814.1,253.79 J3.B9@816.07,255.76
  Signal Layer 2 w10: v2(625,518) 522,518 504,536 504,580 523,599 630,599 696,533 696,251 655,210 v2(655,60)
  Bottom Layer w10: U2.13@499.84,463.23 499.84,493.16 481,512 C26.2@481,539.38 ; v2(504,535) 485.38,535 C26.2@481,539.38 ; C16.2@529,539.38 C26.2@481,539.38 ; U2.15@539.21,463.23 539.21,480.45 562.76,504 620,504 625,509 v2(625,518) C25.1@625,539.38
CSP_1: R4.1 U1.14 | length 120.1
  Bottom Layer w10: U1.14@521.69,975.74 521.69,1004.69 549.06,1032.06 565.68,1032.06 R4.1@591,1057.38
CSP_2: R17.1 U2.14 | length 102
  Bottom Layer w10: U2.14@519.53,463.23 519.53,485.38 573.53,539.38 R17.1@577,539.38
CTL1_1: R7.1 R9.2 U1.5 | length 789.6
  Signal Layer 2 w10: v2(368,892) 389.91,892 398,900.09 398,950.48 446.52,999 606,999 645,960 645,876 v2(616,847)
  Bottom Layer w10: R9.2@265,941.38 315.28,891.09 U1.5@397.67,891.09 ; v2(616,847) 616,778.38 615,777.38 R7.1@667.38,725
CTL1_2: R20.1 R22.2 U2.5 | length 683.6
  Signal Layer 1 w10: v2(338,380) 338,410 400,472 574.17,472 595,451.17 595,369 v2(632,332)
  Bottom Layer w10: R22.2@291,409.38 291,400 312.42,378.58 U2.5@395.51,378.58 ; v2(632,332) 632,278.38 R20.1@668.38,242
CTL2_1: R6.1 R8.2 U1.6 | length 704.9
  Signal Layer 2 w10: v2(368,920) 368,965 420,1017 619.5,1017 664,972.5 664,838.38 v2(633,807.38)
  Bottom Layer w10: R8.2@313,941.38 347.1,941.38 377.69,910.78 U1.6@397.67,910.78 ; v2(633,807.38) R6.1@667.38,773
CTL2_2: R19.1 R21.2 U2.6 | length 603.8
  Signal Layer 1 w10: v2(356,400) 409.57,453.57 568.55,453.57 578,444.13 578,357 610,325 v2(610,304)
  Bottom Layer w10: R21.2@332,409.38 346.62,409.38 v2(356,400) 357.73,398.27 U2.6@395.51,398.27 ; v2(610,304) 610,268 634,244 634,228.38 R19.1@668.38,194
DATA_IN_1_N: J2.A7 J2.B7 U1.17 | length 266
  Signal Layer 1 w10: v2(607.36,958) 727,958 v2(784,901) 788.54,901 814.29,875.25 J2.B7@815.07,875.25
  Bottom Layer w10: U1.17@586.65,950.15 599.51,950.15 v2(607.36,958)
DATA_IN_1_P: J2.A6 J2.B6 U1.18 | length 265.8
  Signal Layer 1 w10: v2(613,938) 708.62,938 765.62,881 v2(784,881)
  Bottom Layer w10: U1.18@586.65,930.46 605.46,930.46 v2(613,938) ; v2(784,881) 788.04,881 813.79,906.75 J2.B6@815.07,906.75
DATA_IN_2_N: J3.A7 J3.B7 U2.17 | length 308.3
  Signal Layer 1 w10: v2(639,455) 642,455 v2(784,313)
  Bottom Layer w10: U2.17@584.49,437.64 621.64,437.64 v2(639,455) ; v2(784,313) 789.04,313 814.79,287.25 J3.B7@816.07,287.25
DATA_IN_2_P: J3.A6 J3.B6 U2.18 | length 304
  Signal Layer 1 w10: v2(639,430) 642.96,430 779.96,293 v2(785,293) 789.54,293 815.29,318.75 J3.B6@816.07,318.75
  Bottom Layer w10: U2.18@584.49,417.95 625.99,417.95 638.04,430 v2(639,430)
NetC1_2: C1.2 R1.2 | length 82.9
  Top Layer w30: R1.2@498.09,651 507.59,660.5 C1.2@577,660.5
NetC2_1: C2.1 C6.1 C7.1 L1.2 R3.1 R4.2 | length 108.8
  Top Layer w10: R3.1@491.91,1128 500.91,1119 v2(529,1119)
  Bottom Layer w10: v2(529,1119) 540.38,1107.62 C2.1@543,1107.62 546,1104.62 R4.2@591,1104.62
NetC5_1: C5.1 R2.2 | length 52.5
  Bottom Layer w10: R2.2@368,670.38 420,670.38 C5.1@420.38,670
NetC5_2: C5.2 L1.1 R1.1 U1.28 U1.29 U1.30 U1.31 | length 55
  Top Layer w30: R1.1@383.91,651 383.91,705.91 384,706
  other v4: 456,725 495,725 455,756 495,757 164,778 211,778 254,778
NetC15_2: C15.2 R14.2 | length 71.4
  Top Layer w30: R14.2@252.09,325 C15.2@323.5,325
NetC16_1: C16.1 C20.1 C21.1 L2.2 R16.1 R17.2 | length 729.1
  Top Layer w10: R16.1@590.91,58 592.91,60 v2(634,60)
  Signal Layer 2 w10: v2(551,578) 621,578 676,523 676,260 634,218 v2(634,60)
  Bottom Layer w10: C16.1@529,586.62 550,586.62 ; v2(551,578) 551,585.62 550,586.62 ; R17.2@577,586.62 550,586.62
NetC19_1: C19.1 R15.2 | length 61.6
  Bottom Layer w10: R15.2@385,172.38 439,172.38 C19.1@444.38,167
NetC19_2: C19.2 L2.1 R14.1 U2.28 U2.29 U2.30 U2.31
  other v4: 95,175 129,175 163,175 445,213 438,240 469,240 500,240
NetR2_1: R2.1 U1.32 | length 92
  Bottom Layer w10: R2.1@368,717.62 368,718 423.26,773.26 U1.32@423.26,786.76
NetR10_2: R10.2 U1.12 | length 96.3
  Bottom Layer w10: R10.2@447,1057.38 447,1031 482.32,995.68 U1.12@482.32,975.74
NetR11_2: R11.2 U1.11 | length 121.6
  Bottom Layer w10: R11.2@399,1057.38 399,1029 411,1017 434.26,1017 462.63,988.63 U1.11@462.63,975.74
NetR15_1: R15.1 U2.32 | length 58.6
  Bottom Layer w10: R15.1@385,219.62 385,225.18 421.1,261.29 U2.32@421.1,263.29
NetR23_2: R23.2 U2.12 | length 95.7
  Bottom Layer w10: R23.2@433,539.38 433,528.04 480.16,480.88 U2.12@480.16,463.23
